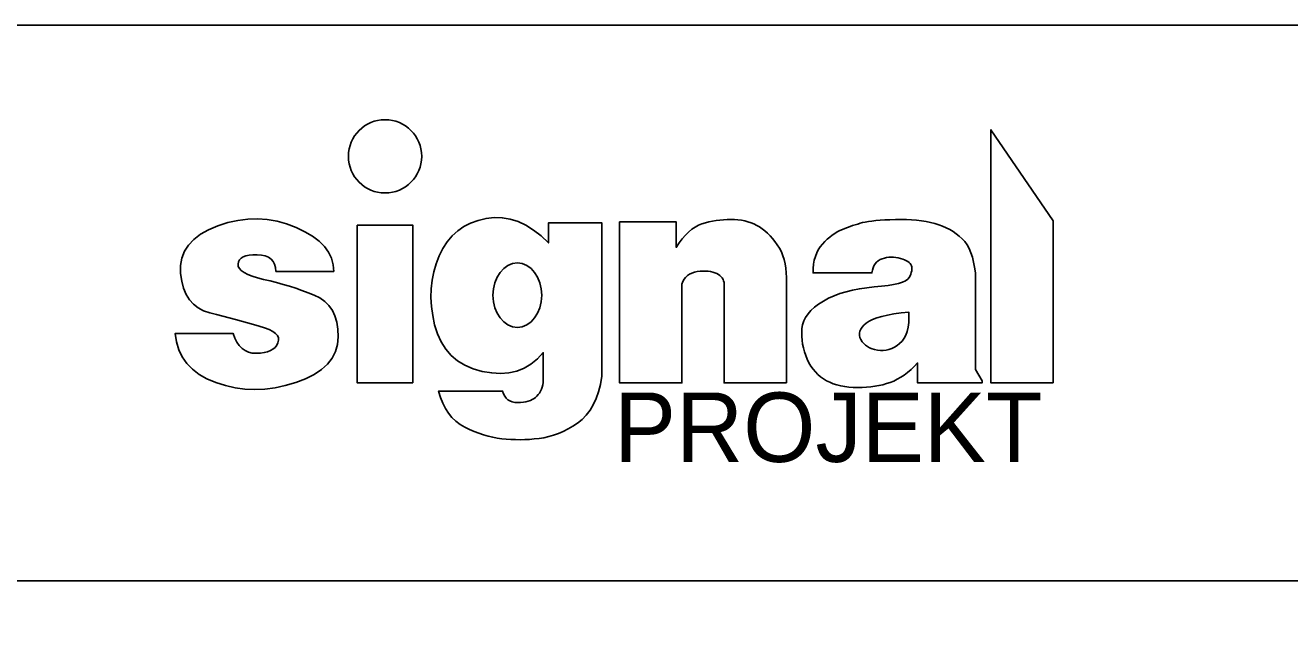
# Model space of a CAD drawing. Extents: x -558358 to -557517, y -1073785 to -1073189.
# Drawn here: x -557597.85 to -557552.36, y -1073654.43 to -1073632.09 of the extents above; entities that cross this region are included whole.
import ezdxf

# ---------------------------------------------------------------- set-up
doc = ezdxf.new("R2010")
doc.units = 0
doc.layers.add('ROZPISKA', color=7, linetype='Continuous')
doc.layers.add('Rozpiska_pole_6', color=7, linetype='Continuous')

msp = doc.modelspace()

# ---------------------------------------------------------------- linework, layer by layer
at = {"layer": 'ROZPISKA'}
for points in [[(-557560.869, -1073644.967), (-557560.869, -1073639.127), (-557563.109, -1073635.847), (-557563.109, -1073644.967), (-557560.869, -1073644.967)], [(-557589.598, -1073645.202), (-557589.236, -1073645.186), (-557588.869, -1073645.138), (-557588.498, -1073645.059), (-557588.122, -1073644.948), (-557587.768, -1073644.812), (-557587.46, -1073644.656), (-557587.199, -1073644.48), (-557586.985, -1073644.284), (-557586.817, -1073644.068), (-557586.697, -1073643.832), (-557586.623, -1073643.576), (-557586.597, -1073643.301), (-557586.607, -1073643.027), (-557586.646, -1073642.778), (-557586.712, -1073642.554), (-557586.806, -1073642.355), (-557586.927, -1073642.18), (-557587.076, -1073642.03), (-557587.253, -1073641.904), (-557587.458, -1073641.804), (-557587.677, -1073641.718), (-557587.899, -1073641.636), (-557588.123, -1073641.558), (-557588.35, -1073641.486), (-557588.579, -1073641.417), (-557588.81, -1073641.353), (-557589.043, -1073641.293), (-557589.279, -1073641.238), (-557589.501, -1073641.183), (-557589.692, -1073641.124), (-557589.852, -1073641.061), (-557589.983, -1073640.994), (-557590.083, -1073640.922), (-557590.152, -1073640.847), (-557590.191, -1073640.768), (-557590.2, -1073640.685), (-557590.183, -1073640.605), (-557590.147, -1073640.537), (-557590.091, -1073640.479), (-557590.015, -1073640.431), (-557589.919, -1073640.395), (-557589.803, -1073640.37), (-557589.668, -1073640.355), (-557589.512, -1073640.351), (-557589.357, -1073640.362), (-557589.222, -1073640.391), (-557589.107, -1073640.439), (-557589.012, -1073640.504), (-557588.937, -1073640.588), (-557588.883, -1073640.69), (-557588.848, -1073640.811), (-557588.834, -1073640.949), (-557586.755, -1073640.949), (-557586.774, -1073640.708), (-557586.836, -1073640.478), (-557586.941, -1073640.261), (-557587.089, -1073640.057), (-557587.28, -1073639.865), (-557587.514, -1073639.686), (-557587.79, -1073639.52), (-557588.11, -1073639.367), (-557588.452, -1073639.237), (-557588.797, -1073639.143), (-557589.145, -1073639.083), (-557589.495, -1073639.058), (-557589.848, -1073639.068), (-557590.203, -1073639.113), (-557590.562, -1073639.193), (-557590.922, -1073639.307), (-557591.26, -1073639.45), (-557591.55, -1073639.612), (-557591.79, -1073639.796), (-557591.983, -1073640), (-557592.126, -1073640.224), (-557592.221, -1073640.469), (-557592.267, -1073640.734), (-557592.265, -1073641.02), (-557592.225, -1073641.302), (-557592.159, -1073641.554), (-557592.067, -1073641.776), (-557591.948, -1073641.969), (-557591.804, -1073642.132), (-557591.633, -1073642.266), (-557591.436, -1073642.37), (-557591.212, -1073642.445), (-557590.977, -1073642.505), (-557590.746, -1073642.565), (-557590.519, -1073642.624), (-557590.295, -1073642.683), (-557590.074, -1073642.741), (-557589.858, -1073642.8), (-557589.645, -1073642.858), (-557589.435, -1073642.916), (-557589.243, -1073642.976), (-557589.081, -1073643.04), (-557588.951, -1073643.109), (-557588.851, -1073643.182), (-557588.783, -1073643.26), (-557588.745, -1073643.343), (-557588.738, -1073643.429), (-557588.762, -1073643.521), (-557588.808, -1073643.609), (-557588.869, -1073643.685), (-557588.945, -1073643.75), (-557589.035, -1073643.803), (-557589.139, -1073643.844), (-557589.257, -1073643.874), (-557589.39, -1073643.893), (-557589.537, -1073643.899), (-557589.686, -1073643.889), (-557589.822, -1073643.856), (-557589.945, -1073643.8), (-557590.056, -1073643.722), (-557590.155, -1073643.62), (-557590.242, -1073643.497), (-557590.316, -1073643.35), (-557590.377, -1073643.182), (-557592.458, -1073643.182), (-557592.414, -1073643.488), (-557592.33, -1073643.771), (-557592.207, -1073644.028), (-557592.045, -1073644.262), (-557591.842, -1073644.472), (-557591.601, -1073644.657), (-557591.319, -1073644.818), (-557590.998, -1073644.954), (-557590.655, -1073645.063), (-557590.307, -1073645.141), (-557589.955, -1073645.187), (-557589.598, -1073645.202)], [(-557580.05, -1073647.009), (-557579.881, -1073647.006), (-557579.711, -1073646.997), (-557579.539, -1073646.984), (-557579.366, -1073646.965), (-557579.192, -1073646.939), (-557579.018, -1073646.9), (-557578.844, -1073646.848), (-557578.67, -1073646.785), (-557578.497, -1073646.71), (-557578.324, -1073646.622), (-557578.152, -1073646.522), (-557577.98, -1073646.41), (-557577.815, -1073646.281), (-557577.667, -1073646.128), (-557577.534, -1073645.952), (-557577.418, -1073645.753), (-557577.317, -1073645.531), (-557577.232, -1073645.286), (-557577.163, -1073645.018), (-557577.109, -1073644.727), (-557577.109, -1073639.207), (-557579.029, -1073639.207), (-557579.029, -1073639.927), (-557579.295, -1073639.673), (-557579.566, -1073639.46), (-557579.84, -1073639.288), (-557580.119, -1073639.157), (-557580.402, -1073639.067), (-557580.69, -1073639.018), (-557580.981, -1073639.01), (-557581.277, -1073639.044), (-557581.564, -1073639.112), (-557581.83, -1073639.209), (-557582.073, -1073639.334), (-557582.295, -1073639.488), (-557582.495, -1073639.67), (-557582.673, -1073639.881), (-557582.83, -1073640.121), (-557582.965, -1073640.388), (-557583.075, -1073640.674), (-557583.16, -1073640.967), (-557583.219, -1073641.267), (-557583.252, -1073641.575), (-557583.259, -1073641.889), (-557583.24, -1073642.211), (-557583.196, -1073642.54), (-557583.125, -1073642.876), (-557583.025, -1073643.199), (-557582.892, -1073643.49), (-557582.727, -1073643.748), (-557582.529, -1073643.974), (-557582.298, -1073644.166), (-557582.035, -1073644.326), (-557581.738, -1073644.454), (-557581.41, -1073644.548), (-557581.073, -1073644.606), (-557580.755, -1073644.624), (-557580.454, -1073644.6), (-557580.171, -1073644.536), (-557579.906, -1073644.432), (-557579.659, -1073644.286), (-557579.429, -1073644.1), (-557579.217, -1073643.873), (-557579.217, -1073644.95), (-557579.236, -1073645.037), (-557579.259, -1073645.119), (-557579.286, -1073645.195), (-557579.319, -1073645.265), (-557579.355, -1073645.33), (-557579.396, -1073645.388), (-557579.442, -1073645.441), (-557579.491, -1073645.489), (-557579.547, -1073645.53), (-557579.61, -1073645.567), (-557579.68, -1073645.598), (-557579.757, -1073645.623), (-557579.841, -1073645.643), (-557579.932, -1073645.658), (-557580.03, -1073645.667), (-557580.135, -1073645.671), (-557580.239, -1073645.666), (-557580.332, -1073645.647), (-557580.415, -1073645.616), (-557580.488, -1073645.571), (-557580.551, -1073645.512), (-557580.604, -1073645.441), (-557580.646, -1073645.356), (-557580.678, -1073645.258), (-557582.986, -1073645.258), (-557582.916, -1073645.485), (-557582.833, -1073645.694), (-557582.736, -1073645.884), (-557582.625, -1073646.056), (-557582.501, -1073646.208), (-557582.362, -1073646.342), (-557582.21, -1073646.457), (-557582.044, -1073646.554), (-557581.872, -1073646.637), (-557581.701, -1073646.711), (-557581.532, -1073646.776), (-557581.364, -1073646.833), (-557581.198, -1073646.882), (-557581.033, -1073646.922), (-557580.87, -1073646.953), (-557580.708, -1073646.975), (-557580.546, -1073646.991), (-557580.382, -1073647.002), (-557580.217, -1073647.008), (-557580.05, -1073647.009)], [(-557570.469, -1073644.967), (-557570.469, -1073641.167), (-557570.472, -1073640.997), (-557570.486, -1073640.834), (-557570.511, -1073640.677), (-557570.547, -1073640.527), (-557570.593, -1073640.384), (-557570.65, -1073640.247), (-557570.718, -1073640.117), (-557570.796, -1073639.993), (-557570.881, -1073639.877), (-557570.968, -1073639.769), (-557571.057, -1073639.669), (-557571.148, -1073639.577), (-557571.241, -1073639.494), (-557571.336, -1073639.418), (-557571.433, -1073639.351), (-557571.532, -1073639.293), (-557571.635, -1073639.241), (-557571.741, -1073639.197), (-557571.852, -1073639.16), (-557571.967, -1073639.129), (-557572.086, -1073639.106), (-557572.21, -1073639.089), (-557572.338, -1073639.079), (-557572.47, -1073639.077), (-557572.604, -1073639.08), (-557572.736, -1073639.088), (-557572.868, -1073639.101), (-557572.998, -1073639.119), (-557573.127, -1073639.142), (-557573.255, -1073639.17), (-557573.381, -1073639.202), (-557573.507, -1073639.24), (-557573.63, -1073639.288), (-557573.752, -1073639.353), (-557573.871, -1073639.434), (-557573.987, -1073639.532), (-557574.101, -1073639.646), (-557574.213, -1073639.777), (-557574.322, -1073639.924), (-557574.429, -1073640.087), (-557574.429, -1073639.167), (-557576.469, -1073639.167), (-557576.469, -1073644.967), (-557574.229, -1073644.967), (-557574.229, -1073641.407), (-557574.195, -1073641.316), (-557574.15, -1073641.235), (-557574.096, -1073641.164), (-557574.032, -1073641.103), (-557573.958, -1073641.052), (-557573.874, -1073641.011), (-557573.78, -1073640.98), (-557573.676, -1073640.959), (-557573.57, -1073640.946), (-557573.469, -1073640.939), (-557573.374, -1073640.938), (-557573.283, -1073640.944), (-557573.198, -1073640.955), (-557573.119, -1073640.973), (-557573.044, -1073640.996), (-557572.975, -1073641.026), (-557572.913, -1073641.061), (-557572.859, -1073641.099), (-557572.813, -1073641.141), (-557572.776, -1073641.187), (-557572.747, -1073641.237), (-557572.726, -1073641.29), (-557572.713, -1073641.347), (-557572.709, -1073641.407), (-557572.709, -1073644.967), (-557570.469, -1073644.967)], [(-557567.906, -1073645.131), (-557567.745, -1073645.128), (-557567.587, -1073645.12), (-557567.434, -1073645.105), (-557567.285, -1073645.085), (-557567.14, -1073645.06), (-557567, -1073645.028), (-557566.864, -1073644.991), (-557566.732, -1073644.948), (-557566.604, -1073644.896), (-557566.477, -1073644.835), (-557566.351, -1073644.763), (-557566.228, -1073644.681), (-557566.106, -1073644.588), (-557565.985, -1073644.485), (-557565.866, -1073644.371), (-557565.749, -1073644.247), (-557565.749, -1073644.967), (-557563.429, -1073644.967), (-557563.429, -1073644.887), (-557563.669, -1073644.487), (-557563.669, -1073641.007), (-557563.696, -1073640.803), (-557563.731, -1073640.612), (-557563.777, -1073640.437), (-557563.832, -1073640.276), (-557563.896, -1073640.129), (-557563.97, -1073639.997), (-557564.054, -1073639.879), (-557564.147, -1073639.775), (-557564.248, -1073639.683), (-557564.355, -1073639.597), (-557564.469, -1073639.518), (-557564.589, -1073639.446), (-557564.715, -1073639.381), (-557564.847, -1073639.323), (-557564.986, -1073639.272), (-557565.131, -1073639.228), (-557565.283, -1073639.19), (-557565.442, -1073639.158), (-557565.608, -1073639.131), (-557565.782, -1073639.11), (-557565.962, -1073639.095), (-557566.15, -1073639.086), (-557566.346, -1073639.082), (-557566.548, -1073639.085), (-557566.747, -1073639.091), (-557566.931, -1073639.099), (-557567.1, -1073639.109), (-557567.254, -1073639.122), (-557567.394, -1073639.137), (-557567.519, -1073639.154), (-557567.63, -1073639.174), (-557567.725, -1073639.195), (-557567.814, -1073639.219), (-557567.903, -1073639.245), (-557567.993, -1073639.272), (-557568.084, -1073639.302), (-557568.175, -1073639.333), (-557568.268, -1073639.367), (-557568.36, -1073639.402), (-557568.454, -1073639.44), (-557568.547, -1073639.481), (-557568.639, -1073639.53), (-557568.73, -1073639.585), (-557568.821, -1073639.647), (-557568.91, -1073639.716), (-557568.998, -1073639.792), (-557569.085, -1073639.875), (-557569.171, -1073639.964), (-557569.251, -1073640.062), (-557569.321, -1073640.169), (-557569.379, -1073640.285), (-557569.427, -1073640.411), (-557569.464, -1073640.546), (-557569.49, -1073640.69), (-557569.505, -1073640.844), (-557569.509, -1073641.007), (-557567.389, -1073641.007), (-557567.374, -1073640.911), (-557567.35, -1073640.824), (-557567.317, -1073640.746), (-557567.275, -1073640.677), (-557567.225, -1073640.617), (-557567.167, -1073640.567), (-557567.099, -1073640.525), (-557567.023, -1073640.493), (-557566.943, -1073640.469), (-557566.862, -1073640.451), (-557566.78, -1073640.439), (-557566.698, -1073640.435), (-557566.616, -1073640.436), (-557566.532, -1073640.445), (-557566.449, -1073640.459), (-557566.364, -1073640.481), (-557566.284, -1073640.506), (-557566.213, -1073640.534), (-557566.15, -1073640.564), (-557566.097, -1073640.596), (-557566.051, -1073640.63), (-557566.015, -1073640.666), (-557565.987, -1073640.705), (-557565.969, -1073640.745), (-557565.957, -1073640.788), (-557565.952, -1073640.834), (-557565.953, -1073640.883), (-557565.961, -1073640.934), (-557565.974, -1073640.988), (-557565.994, -1073641.045), (-557566.021, -1073641.105), (-557566.053, -1073641.168), (-557566.104, -1073641.229), (-557566.185, -1073641.285), (-557566.296, -1073641.335), (-557566.438, -1073641.381), (-557566.61, -1073641.421), (-557566.812, -1073641.456), (-557567.045, -1073641.485), (-557567.308, -1073641.509), (-557567.58, -1073641.536), (-557567.839, -1073641.573), (-557568.086, -1073641.621), (-557568.321, -1073641.68), (-557568.544, -1073641.749), (-557568.755, -1073641.828), (-557568.953, -1073641.918), (-557569.139, -1073642.019), (-557569.308, -1073642.127), (-557569.456, -1073642.24), (-557569.584, -1073642.357), (-557569.69, -1073642.479), (-557569.776, -1073642.605), (-557569.841, -1073642.735), (-557569.885, -1073642.871), (-557569.908, -1073643.01), (-557569.916, -1073643.152), (-557569.915, -1073643.292), (-557569.905, -1073643.431), (-557569.886, -1073643.569), (-557569.858, -1073643.705), (-557569.821, -1073643.841), (-557569.775, -1073643.975), (-557569.72, -1073644.108), (-557569.657, -1073644.237), (-557569.587, -1073644.356), (-557569.51, -1073644.466), (-557569.426, -1073644.568), (-557569.335, -1073644.66), (-557569.238, -1073644.744), (-557569.133, -1073644.819), (-557569.022, -1073644.885), (-557568.904, -1073644.943), (-557568.78, -1073644.993), (-557568.65, -1073645.035), (-557568.513, -1073645.07), (-557568.371, -1073645.097), (-557568.222, -1073645.116), (-557568.067, -1073645.127), (-557567.906, -1073645.131)], [(-557583.909, -1073644.967), (-557583.909, -1073639.287), (-557585.909, -1073639.287), (-557585.909, -1073644.967), (-557583.909, -1073644.967)], [(-557567.191, -1073643.787), (-557567.294, -1073643.766), (-557567.388, -1073643.738), (-557567.475, -1073643.702), (-557567.554, -1073643.659), (-557567.625, -1073643.607), (-557567.688, -1073643.548), (-557567.743, -1073643.481), (-557567.789, -1073643.407), (-557567.824, -1073643.329), (-557567.842, -1073643.252), (-557567.843, -1073643.176), (-557567.827, -1073643.101), (-557567.795, -1073643.027), (-557567.746, -1073642.954), (-557567.68, -1073642.881), (-557567.597, -1073642.81), (-557567.494, -1073642.742), (-557567.365, -1073642.679), (-557567.211, -1073642.621), (-557567.032, -1073642.568), (-557566.828, -1073642.521), (-557566.599, -1073642.479), (-557566.344, -1073642.443), (-557566.064, -1073642.412), (-557566.06, -1073642.61), (-557566.069, -1073642.792), (-557566.091, -1073642.958), (-557566.125, -1073643.108), (-557566.173, -1073643.241), (-557566.233, -1073643.359), (-557566.306, -1073643.46), (-557566.393, -1073643.545), (-557566.486, -1073643.617), (-557566.582, -1073643.676), (-557566.679, -1073643.724), (-557566.778, -1073643.76), (-557566.878, -1073643.784), (-557566.981, -1073643.797), (-557567.085, -1073643.798), (-557567.191, -1073643.787)]]:
    msp.add_lwpolyline(points, dxfattribs=at)
msp.add_circle((-557584.909, -1073636.807), 1.32, dxfattribs=at)
msp.add_ellipse((-557580.149, -1073641.807), major_axis=(0, 1.16), ratio=0.758621, dxfattribs=at)
at = {"layer": 'Rozpiska_pole_6'}
msp.add_line((-557706.534, -1073652.088), (-557536.534, -1073652.088), dxfattribs=at)
msp.add_lwpolyline([(-557706.534, -1073632.088), (-557536.534, -1073632.088), (-557536.534, -1073682.088), (-557706.534, -1073682.088)], close=True, dxfattribs=at)

# ---------------------------------------------------------------- texts
at = {"layer": 'ROZPISKA'}
msp.add_text('PROJEKT', height=2.5, dxfattribs=at).set_placement((-557576.669, -1073647.81))

doc.saveas('drawing.dxf')
